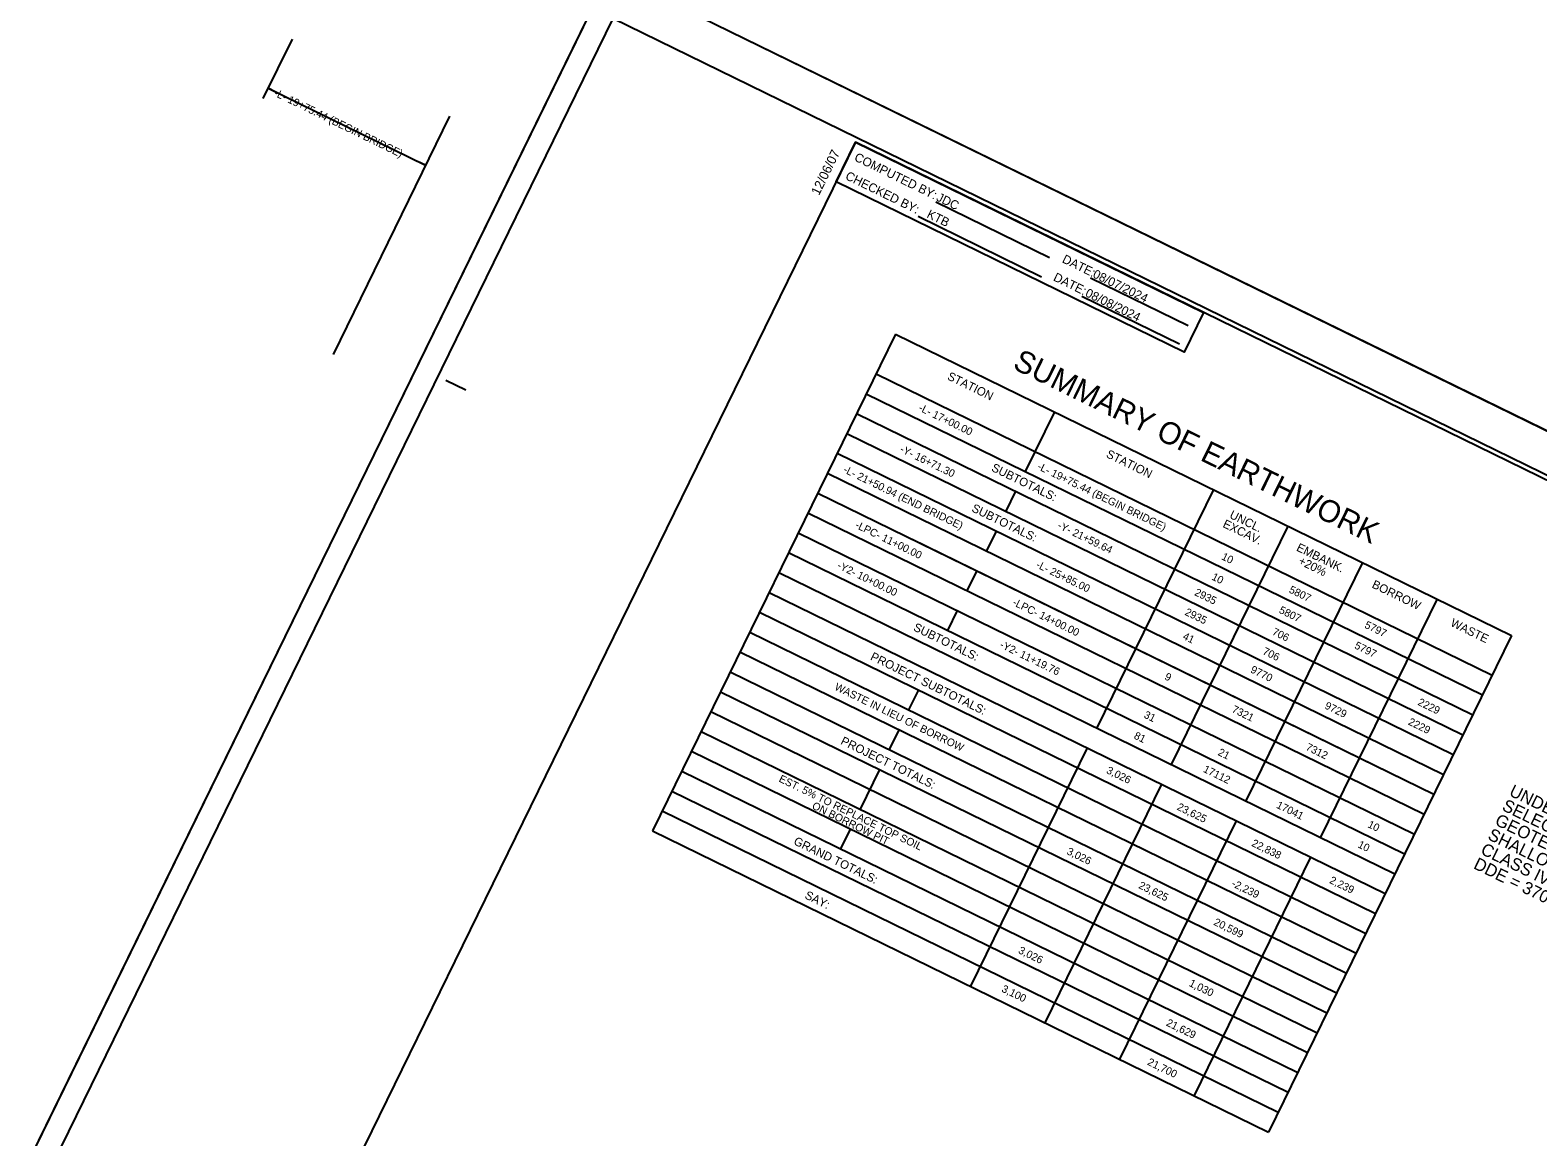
# Model space of a CAD drawing. Extents: x 1523741 to 1527628, y 632733 to 635404.
# Drawn here: x 1525788 to 1526640, y 633803 to 634429 of the extents above; entities that cross this region are included whole.
import ezdxf

# ---------------------------------------------------------------- set-up
doc = ezdxf.new("R2010")
doc.units = 0
for name, color, linetype in [('Scratch_Level_0', 7, 'Continuous'), ('Sheet Cutting Line CELL', 7, 'Continuous'), ('Sheet Data Field CELL', 7, 'Continuous'), ('Sheet Plot Border Inside CELL', 7, 'Continuous'), ('Sheet Plot Border Outside CELL', 7, 'Continuous'), ('Sheet Summary Combination CELL', 7, 'Continuous'), ('Sheet Summary Combination Grid CELL', 7, 'Continuous')]:
    doc.layers.add(name, color=color, linetype=linetype)

msp = doc.modelspace()

# ---------------------------------------------------------------- linework, layer by layer
at = {"layer": 'Scratch_Level_0'}
for p, q in [((1525927.14, 634393.7), (1525922.65, 634395.89)), ((1525922.65, 634395.89), (1526011.72, 634352.33)), ((1526011.72, 634352.33), (1526007.22, 634354.53))]:
    msp.add_line(p, q, dxfattribs=at)
at = {"layer": 'Sheet Cutting Line CELL'}
for p, q in [((1526115.65, 634461.22), (1525632.37, 633473.07)), ((1527628.42, 633721.36), (1526115.65, 634461.22))]:
    msp.add_line(p, q, dxfattribs=at)
at = {"layer": 'Sheet Plot Border Inside CELL'}
msp.add_lwpolyline([(1527614.51, 633703.17), (1526117.47, 634435.34), (1525653.91, 633487.53), (1527150.96, 632755.35)], close=True, dxfattribs=at)
at = {"layer": 'Sheet Plot Border Outside CELL'}
msp.add_lwpolyline([(1527628.42, 633721.36), (1526115.65, 634461.22), (1525632.37, 633473.07), (1527145.14, 632733.21)], close=True, dxfattribs=at)
at = {"layer": 'Sheet Summary Combination CELL'}
for p, q in [((1526300.11, 634331.6), (1526364.39, 634300.16)), ((1526290.07, 634323.48), (1526359.87, 634289.35)), ((1526387.5, 634288.69), (1526442.65, 634261.72)), ((1526382.58, 634278.3), (1526437.73, 634251.32)), ((1526023.17, 634230.94), (1526034.4, 634225.44)), ((1526415.3, 634189.33), (1526415.3, 634189.33)), ((1526420.87, 634186.5), (1526420.87, 634186.5)), ((1526429.09, 634182.7), (1526429.09, 634182.7)), ((1526434.08, 634180.15), (1526434.08, 634180.15))]:
    msp.add_line(p, q, dxfattribs=at)
for points in [[(1527602.16, 633706.37), (1526254.69, 634365.39), (1525793.37, 633422.16), (1527140.85, 632763.14)], [(1526254.69, 634365.39), (1526451.42, 634269.17), (1526440.44, 634246.72), (1526243.7, 634342.93)]]:
    msp.add_lwpolyline(points, close=True, dxfattribs=at)
at = {"layer": 'Sheet Summary Combination Grid CELL'}
for p, q in [((1525936.24, 634423.69), (1525919.77, 634390)), ((1526025.31, 634380.13), (1525959.41, 634245.38)), ((1526277.25, 634256.91), (1526139.95, 633976.18)), ((1526277.25, 634256.91), (1526625.44, 634086.62)), ((1526266.27, 634234.45), (1526614.46, 634064.16)), ((1526260.78, 634223.22), (1526608.96, 634052.93)), ((1526255.28, 634211.99), (1526603.47, 634041.7)), ((1526367.08, 634212.97), (1526350.61, 634179.28)), ((1526249.79, 634200.76), (1526597.98, 634030.47)), ((1526244.3, 634189.53), (1526592.49, 634019.24)), ((1526238.81, 634178.3), (1526587, 634008.01)), ((1526233.32, 634167.07), (1526581.5, 633996.78)), ((1526345.12, 634168.06), (1526339.62, 634156.83)), ((1526456.91, 634169.04), (1526391.01, 634034.29)), ((1526227.82, 634155.85), (1526576.01, 633985.55)), ((1526222.33, 634144.62), (1526570.52, 633974.33)), ((1526334.13, 634145.6), (1526328.64, 634134.37)), ((1526499.05, 634148.43), (1526433.14, 634013.68)), ((1526216.84, 634133.39), (1526565.03, 633963.1)), ((1526286.63, 634141), (1526581.5, 633996.78)), ((1526541.18, 634127.83), (1526475.27, 633993.08)), ((1526211.35, 634122.16), (1526559.54, 633951.87)), ((1526323.15, 634123.14), (1526317.66, 634111.91)), ((1526205.86, 634110.93), (1526554.04, 633940.64)), ((1526200.37, 634099.7), (1526548.55, 633929.41)), ((1526312.16, 634100.68), (1526306.67, 634089.45)), ((1526583.31, 634107.22), (1526517.41, 633972.47)), ((1526194.87, 634088.47), (1526543.06, 633918.18)), ((1526625.44, 634086.62), (1526488.14, 633805.89)), ((1526189.38, 634077.24), (1526537.57, 633906.95)), ((1526183.89, 634066.01), (1526532.08, 633895.72)), ((1526178.4, 634054.79), (1526526.59, 633884.49)), ((1526290.2, 634055.77), (1526284.71, 634044.54)), ((1526172.91, 634043.56), (1526521.09, 633873.26)), ((1526167.41, 634032.33), (1526515.6, 633862.04)), ((1526279.21, 634033.31), (1526273.72, 634022.08)), ((1526385.52, 634023.06), (1526319.62, 633888.31)), ((1526161.92, 634021.1), (1526510.11, 633850.81)), ((1526156.43, 634009.87), (1526504.62, 633839.58)), ((1526268.23, 634010.85), (1526257.25, 633988.39)), ((1526150.94, 633998.64), (1526499.13, 633828.35)), ((1526427.65, 634002.45), (1526361.75, 633867.71)), ((1526145.45, 633987.41), (1526493.63, 633817.12)), ((1526469.78, 633981.85), (1526403.88, 633847.1)), ((1526139.95, 633976.18), (1526488.14, 633805.89)), ((1526251.75, 633977.16), (1526246.26, 633965.93)), ((1526511.91, 633961.24), (1526446.01, 633826.5))]:
    msp.add_line(p, q, dxfattribs=at)

# ---------------------------------------------------------------- texts
at = {"layer": 'Sheet Data Field CELL'}
for s, p in [('JDC', (1526299.97, 634332.56)), ('KTB', (1526294.54, 634323.04)), ('08/07/2024', (1526388.34, 634289.17)), ('08/08/2024', (1526384.12, 634278.49))]:
    msp.add_text(s, height=5, rotation=333.93772, dxfattribs=at).set_placement(p)
at = {"layer": 'Sheet Summary Combination CELL'}
for s, height, rotation, p in [('-L- 19+75.44 (BEGIN BRIDGE)', 4.32, 333.93772, (1525925.6, 634391.8)), ('12/06/07', 5.25, 63.93772, (1526234.05, 634334.92)), ('COMPUTED BY:', 4.9998, 333.93772, (1526253.55, 634355.21)), ('CHECKED BY:', 4.9998, 333.93772, (1526248.5, 634344.65)), ('DATE:', 5, 333.93772, (1526371.05, 634297.63)), ('DATE:', 5, 333.93772, (1526366.04, 634287.39)), ('SUMMARY OF EARTHWORK', 12.5001, 333.94965, (1526342.93, 634237.65)), ('STATION', 4.8, 333.93772, (1526306.13, 634231.47)), ('-L- 17+00.00', 4.32, 333.93772, (1526289.94, 634213.87)), ('-Y- 16+71.30', 4.32, 333.93772, (1526279.38, 634190.5)), ('STATION', 4.8, 333.93772, (1526395.95, 634187.51)), ('-L- 21+50.94 (END BRIDGE)', 4.32, 333.93772, (1526247.37, 634178.96)), ('SUBTOTALS:', 4.8, 333.93772, (1526331.06, 634179.8)), ('-L- 19+75.44 (BEGIN BRIDGE)', 4.32, 333.93772, (1526357.02, 634180.74)), ('SUBTOTALS:', 4.8, 333.93772, (1526319.86, 634156.92)), ('-LPC- 11+00.00', 4.32, 333.93772, (1526254.1, 634147.63)), ('-Y- 21+59.64', 4.32, 333.93772, (1526368.47, 634147.37)), ('EXCAV.', 4.8, 333.93772, (1526461.83, 634148.04)), ('UNCL.', 4.8, 333.93772, (1526465.64, 634153.19)), ('10', 4.32, 333.93772, (1526461.14, 634129.73)), ('EMBANK.', 4.8, 333.93772, (1526503.46, 634134.69)), ('-Y2- 10+00.00', 4.32, 333.93772, (1526243.94, 634124.76)), ('-L- 25+85.00', 4.32, 333.93772, (1526356.34, 634125.2)), ('+20%', 4.8, 333.93772, (1526504.52, 634127.16)), ('10', 4.32, 333.93772, (1526455.56, 634118.31)), ('BORROW', 4.8, 333.93772, (1526546.09, 634113.84)), ('2935', 4.32, 333.93772, (1526445.86, 634109.52)), ('5807', 4.32, 333.93772, (1526499.25, 634111.03)), ('-LPC- 14+00.00', 4.32, 333.93772, (1526343.06, 634103.92)), ('2935', 4.32, 333.93772, (1526440.42, 634098.39)), ('5807', 4.32, 333.93772, (1526493.62, 634099.52)), ('SUBTOTALS:', 4.8, 333.93772, (1526286.94, 634089.6)), ('706', 4.32, 333.93772, (1526489.77, 634087.25)), ('5797', 4.32, 333.93772, (1526541.98, 634091.11)), ('WASTE', 4.8, 333.93772, (1526590.51, 634092.12)), ('-Y2- 11+19.76', 4.32, 333.93772, (1526335.81, 634079.97)), ('41', 4.32, 333.93772, (1526439.19, 634084.69)), ('5797', 4.32, 333.93772, (1526536.29, 634079.48)), ('PROJECT SUBTOTALS:', 4.8, 333.93772, (1526262.68, 634073.04)), ('706', 4.32, 333.93772, (1526484.38, 634076.23)), ('9', 4.32, 333.93772, (1526428.99, 634061.9)), ('9770', 4.32, 333.93772, (1526477.5, 634065.87)), ('WASTE IN LIEU OF BORROW', 4.32, 333.93772, (1526242.46, 634056.09)), ('9729', 4.32, 333.93772, (1526519.47, 634045.48)), ('2229', 4.32, 333.93772, (1526572.09, 634047.47)), ('31', 4.32, 333.93772, (1526417.23, 634040.32)), ('7321', 4.32, 333.93772, (1526466.97, 634043.41)), ('2229', 4.32, 333.93772, (1526566.66, 634036.37)), ('81', 4.32, 333.93772, (1526411.64, 634028.51)), ('PROJECT TOTALS:', 4.8, 333.93772, (1526245.9, 634025.36)), ('21', 4.32, 333.93772, (1526459.11, 634019.14)), ('7312', 4.32, 333.93772, (1526508.76, 634022.07)), ('EST. 5% TO REPLACE TOP SOIL', 4.32, 333.93772, (1526210.96, 634004.14)), ('3,026', 4.32, 333.93772, (1526396.08, 634008.92)), ('17112', 4.32, 333.93772, (1526450.77, 634009.62)), ('UNDERCUT EXCAVATION = 450 CY (CONTINGENCY)', 7, 333.93772, (1526623.58, 633996.34)), (' ON BORROW PIT', 4.32, 333.93772, (1526228.24, 633989.59)), ('23,625', 4.32, 333.93772, (1526435.97, 633988.27)), ('17041', 4.32, 333.93772, (1526492.19, 633989.3)), ('SELECT GRANULAR MATERIAL = 400 CY (CONTINGENCY)', 7, 333.93772, (1526619.55, 633988.09)), ('10', 4.32, 333.93772, (1526543.73, 633978.35)), ('GEOTEXTILE FOR SOIL STABILIZATION = 700 SY (CONTINGENCY)', 7, 333.93772, (1526615.51, 633979.85)), ('GRAND TOTALS:', 4.8, 333.93772, (1526219.29, 633968.72)), ('22,838', 4.32, 333.93772, (1526478.15, 633967.77)), ('SHALLOW UNDERCUT = 100 CY (CONTINGENCY)', 7, 333.93772, (1526611.48, 633971.61)), ('3,026', 4.32, 333.93772, (1526373.68, 633963.13)), ('10', 4.32, 333.93772, (1526538.16, 633966.96)), ('CLASS IV SUBGRADE STABILIZATION = 200 TON (CONTINGENCY)', 7, 333.93772, (1526607.45, 633963.36)), ('DDE = 370 CY', 7, 333.93772, (1526603.42, 633955.12)), ('23,625', 4.32, 333.93772, (1526414.28, 633943.92)), ('-2,239', 4.32, 333.93772, (1526466.82, 633945.01)), ('2,239', 4.32, 333.93772, (1526522.18, 633946.82)), ('SAY:', 4.8, 333.93772, (1526225.58, 633938.18)), ('20,599', 4.32, 333.93772, (1526456.72, 633923.14)), ('3,026', 4.32, 333.93772, (1526346.32, 633907.18)), ('3,100', 4.32, 333.93772, (1526336.82, 633885.43)), ('1,030', 4.32, 333.93772, (1526442.8, 633888.63)), ('21,629', 4.32, 333.93772, (1526429.88, 633866.24)), ('21,700', 4.32, 333.93772, (1526419.24, 633844.1))]:
    msp.add_text(s, height=height, rotation=rotation, dxfattribs=at).set_placement(p)

doc.saveas('drawing.dxf')
